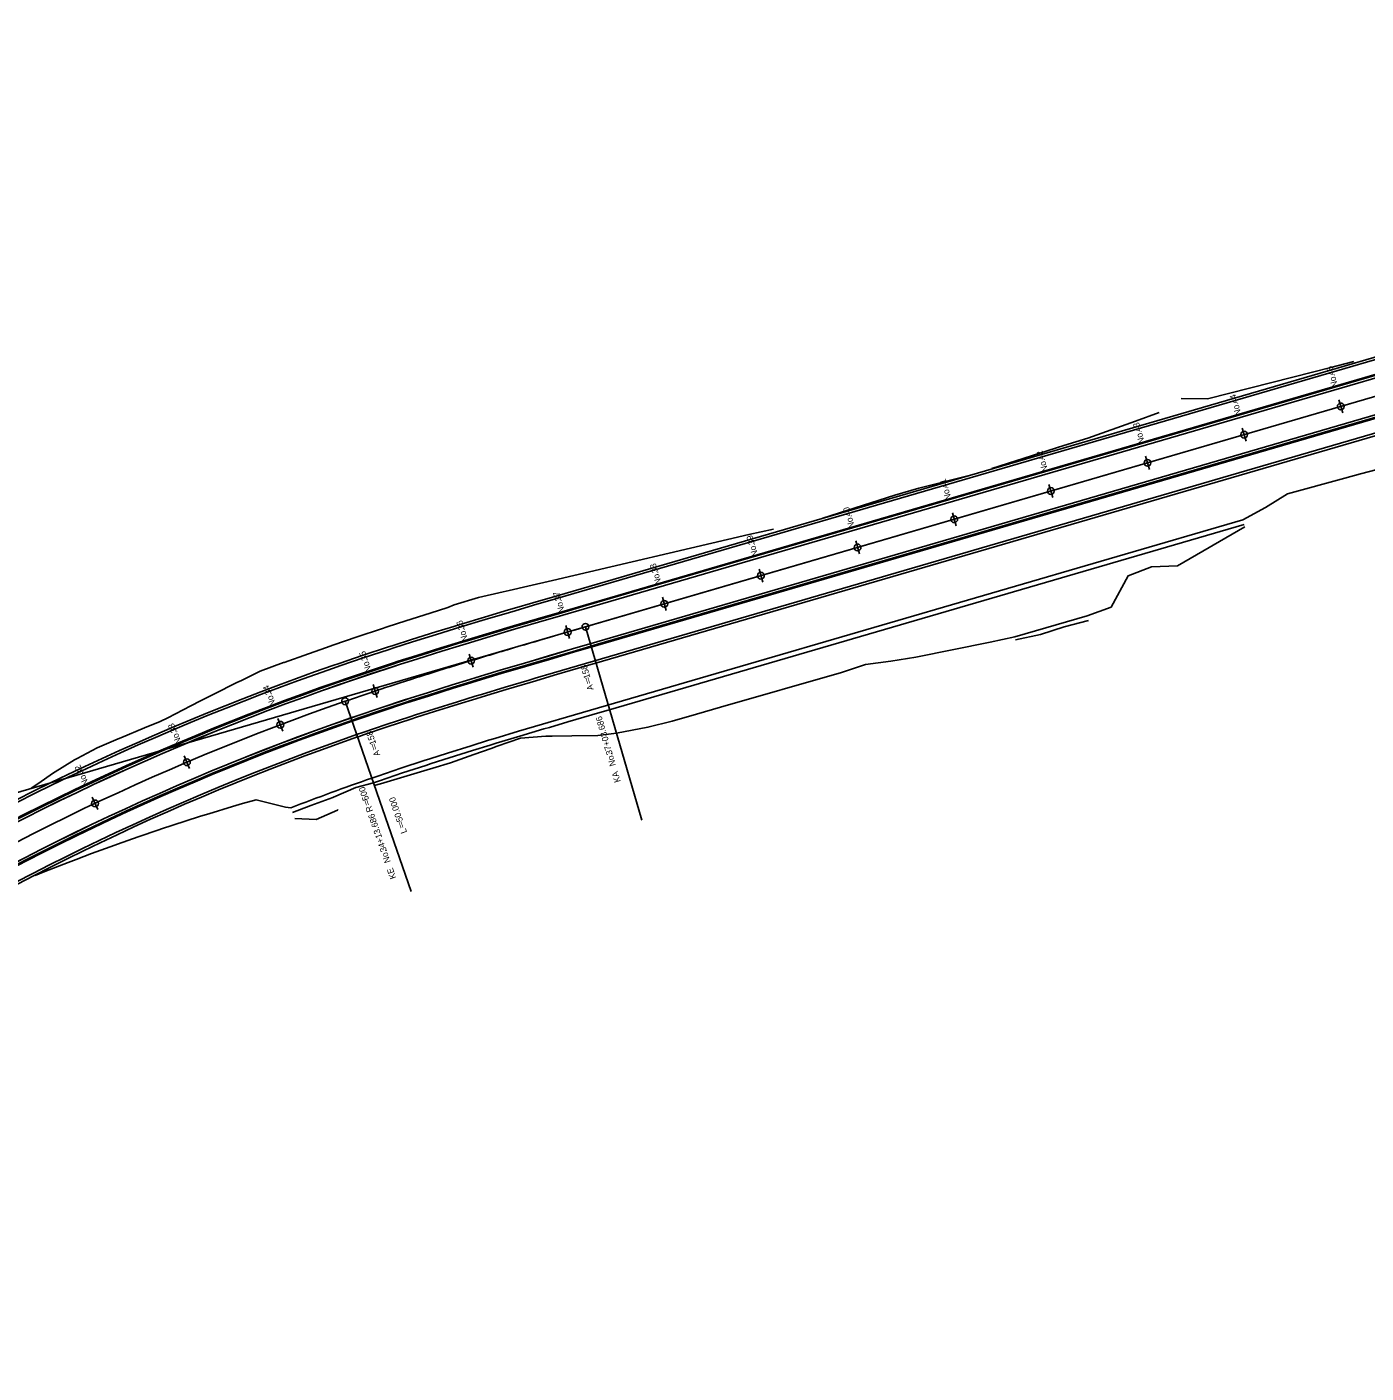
# Model space of a CAD drawing. Extents: x 46424 to 47578, y 10417 to 11548.
# Drawn here: x 46662.8 to 46928.8, y 10813.5 to 11080.9 of the extents above; entities that cross this region are included whole.
import ezdxf

# ---------------------------------------------------------------- set-up
doc = ezdxf.new("R2010")
doc.units = 0
for name, color, linetype in [('Default', 7, 'Continuous'), ('出典（地理院地図Vector）', 7, 'Continuous'), ('河川_人工水路(地下)（地理院地図Vector）', 7, 'Continuous'), ('現況_地形', 7, 'Continuous'), ('現況_地形_三角形', 7, 'Continuous'), ('現況_地形_三角形_頂点', 7, 'Continuous'), ('現況_地形_低い点', 7, 'Continuous'), ('現況_地形_単点標高', 7, 'Continuous'), ('現況_地形_等高線_マイナー', 7, 'Continuous'), ('等高線等深線_等高線_補助曲線通常部（地理院地図Vector）', 7, 'Continuous'), ('設計図面_測点 ラベル メジャー', 7, 'Continuous'), ('設計図面_測点 印 メジャー', 7, 'Continuous')]:
    doc.layers.add(name, color=color, linetype=linetype)

msp = doc.modelspace()

# ---------------------------------------------------------------- linework, layer by layer
at = {"layer": 'Default'}
for p, q in [((46606.99, 10913.06), (47182.22, 11080.85)), ((46773.73, 10961.69), (47084.04, 11052.21)), ((46923.79, 11005.47), (46923.79, 11005.47)), ((46904.59, 10999.87), (46904.59, 10999.87)), ((46885.39, 10994.27), (46885.39, 10994.27)), ((46866.19, 10988.67), (46866.19, 10988.67)), ((46846.99, 10983.06), (46846.99, 10983.06)), ((46827.79, 10977.46), (46827.79, 10977.46)), ((46808.59, 10971.86), (46808.59, 10971.86)), ((46789.39, 10966.26), (46789.39, 10966.26)), ((46770.19, 10960.66), (46770.19, 10960.66)), ((46773.73, 10961.69), (46773.73, 10961.69)), ((46773.73, 10961.69), (46784.93, 10923.29)), ((46751.02, 10954.98), (46751.02, 10954.98)), ((46725.98, 10946.9), (46725.98, 10946.9)), ((46725.98, 10946.9), (46739.09, 10909.1)), ((46725.98, 10946.9), (46739.09, 10909.1)), ((46731.96, 10948.93), (46731.96, 10948.93)), ((46713.11, 10942.24), (46713.11, 10942.24)), ((46694.55, 10934.8), (46694.55, 10934.8)), ((46676.3, 10926.62), (46676.3, 10926.62))]:
    msp.add_line(p, q, dxfattribs=at)
for centre in [(46923.79, 11005.47), (46904.59, 10999.87), (46885.39, 10994.27), (46866.19, 10988.67), (46846.99, 10983.06), (46827.79, 10977.46), (46808.59, 10971.86), (46789.39, 10966.26), (46770.19, 10960.66), (46773.73, 10961.69), (46751.02, 10954.98), (46731.96, 10948.93), (46725.98, 10946.9), (46713.11, 10942.24), (46694.55, 10934.8), (46676.3, 10926.62)]:
    msp.add_circle(centre, 0.675, dxfattribs=at)
msp.add_arc((46889.81, 10474.5), 500, 109.127, 136.5076, dxfattribs=at)
msp.add_arc((46889.81, 10474.5), 500, 109.127, 136.5076, dxfattribs=at)
msp.add_open_spline([(46725.98, 10946.9), (46727.95, 10947.58), (46731.89, 10948.92), (46739.81, 10951.51), (46749.76, 10954.62), (46759.74, 10957.6), (46767.73, 10959.94), (46771.73, 10961.11), (46773.73, 10961.69)], degree=3, dxfattribs=at)
msp.add_open_spline([(46725.98, 10946.9), (46727.95, 10947.58), (46731.89, 10948.92), (46739.81, 10951.51), (46749.76, 10954.62), (46759.74, 10957.6), (46767.73, 10959.94), (46771.73, 10961.11), (46773.73, 10961.69)], degree=3, dxfattribs=at)
at = {"layer": '出典（地理院地図Vector）'}
for points in [[(46723.52, 10953.98), (46724.78, 10954.42), (46729.58, 10956.04), (46734.39, 10957.63), (46735.53, 10957.99), (46739.2, 10959.17), (46744.02, 10960.67), (46747.57, 10961.77), (46748.84, 10962.15), (46753.66, 10963.6), (46758.47, 10965.04), (46759.61, 10965.37), (46763.28, 10966.45), (46768.09, 10967.86), (46772.89, 10969.26), (47081.94, 11059.41)], [(46728.44, 10939.81), (46729.66, 10940.23), (46734.33, 10941.81), (46739.02, 10943.36), (46740.14, 10943.72), (46743.73, 10944.87), (46748.46, 10946.35), (46751.95, 10947.42), (46753.2, 10947.8), (46757.96, 10949.23), (46762.73, 10950.65), (46763.86, 10950.99), (46767.51, 10952.06), (46772.3, 10953.46), (46777.09, 10954.86), (47086.14, 11045.01)]]:
    msp.add_lwpolyline(points, dxfattribs=at)
for radius in [507.5, 492.5]:
    msp.add_arc((46889.81, 10474.5), radius, 109.127, 136.5076, dxfattribs=at)
at = {"layer": '河川_人工水路(地下)（地理院地図Vector）'}
msp.add_line((46773.73, 10961.69), (47084.04, 11052.21), dxfattribs=at)
msp.add_arc((46889.81, 10474.5), 500, 109.127, 136.5076, dxfattribs=at)
msp.add_open_spline([(46725.98, 10946.9), (46727.95, 10947.58), (46731.89, 10948.92), (46739.81, 10951.51), (46749.76, 10954.62), (46759.74, 10957.6), (46767.73, 10959.94), (46771.73, 10961.11), (46773.73, 10961.69)], degree=3, dxfattribs=at)
at = {"layer": '現況_地形'}
for points in [[(46724.83, 10950.21), (46726.08, 10950.64), (46730.85, 10952.26), (46735.62, 10953.83), (46736.76, 10954.2), (46740.41, 10955.36), (46745.2, 10956.86), (46748.74, 10957.95), (46750, 10958.33), (46754.8, 10959.78), (46759.6, 10961.21), (46760.74, 10961.55), (46764.41, 10962.63), (46769.21, 10964.03), (46774.01, 10965.43), (47083.06, 11055.58)], [(46724.83, 10950.2), (46726.08, 10950.63), (46730.85, 10952.25), (46735.63, 10953.82), (46736.76, 10954.19), (46740.41, 10955.35), (46745.2, 10956.85), (46748.74, 10957.94), (46750, 10958.33), (46754.8, 10959.77), (46759.61, 10961.2), (46760.75, 10961.54), (46764.41, 10962.62), (46769.21, 10964.02), (46774.01, 10965.42), (47083.06, 11055.57)], [(46727.13, 10943.59), (46728.36, 10944.02), (46733.06, 10945.61), (46737.79, 10947.16), (46738.91, 10947.53), (46742.52, 10948.68), (46747.27, 10950.17), (46750.78, 10951.25), (46752.04, 10951.63), (46756.81, 10953.07), (46761.59, 10954.49), (46762.73, 10954.82), (46766.38, 10955.9), (46771.18, 10957.3), (46775.97, 10958.7), (47085.02, 11048.85)], [(46727.13, 10943.58), (46728.36, 10944.01), (46733.07, 10945.6), (46737.79, 10947.15), (46738.91, 10947.52), (46742.53, 10948.67), (46747.28, 10950.16), (46750.79, 10951.24), (46752.04, 10951.62), (46756.81, 10953.06), (46761.59, 10954.48), (46762.73, 10954.81), (46766.38, 10955.89), (46771.18, 10957.29), (46775.98, 10958.69), (47085.03, 11048.84)]]:
    msp.add_lwpolyline(points, dxfattribs=at)
for radius in [503.51, 503.5, 496.5, 496.49]:
    msp.add_arc((46889.81, 10474.5), radius, 109.127, 136.5076, dxfattribs=at)
at = {"layer": '現況_地形_三角形'}
msp.add_lwpolyline([(46854.47, 10993.15), (46864, 10996.17), (46868.77, 10997.68), (46873.54, 10999.2), (46882.98, 11002.55), (46887.68, 11004.29)], dxfattribs=at)
at = {"layer": '現況_地形_三角形_頂点'}
for points in [[(46892.07, 11007.08), (46897.3, 11007.01), (46918.45, 11012.36), (46921.55, 11013.14), (46926.4, 11014.39)], [(46731.27, 10931.64), (46732.47, 10932.05), (46737.07, 10933.61), (46741.69, 10935.13), (46742.79, 10935.49), (46746.34, 10936.62), (46751.02, 10938.08), (46754.48, 10939.15), (46755.72, 10939.53), (46760.44, 10940.95), (46765.18, 10942.36), (46766.31, 10942.69), (46769.94, 10943.76), (46774.72, 10945.16), (46779.52, 10946.56), (46904.32, 10982.96), (46908.81, 10985.42), (46913.22, 10988.14), (46924.6, 10991.25), (46927.69, 10992.09), (46932.55, 10993.31)], [(46820.88, 10983.3), (46835.18, 10987.84), (46839.99, 10989.24), (46849.68, 10991.71)], [(46715.55, 10924.81), (46719.17, 10926.19), (46723.55, 10927.82), (46723.7, 10927.88), (46728.14, 10929.8), (46731.6, 10930.69), (46732.8, 10931.11), (46737.38, 10932.66), (46742, 10934.18), (46743.1, 10934.54), (46746.64, 10935.67), (46751.31, 10937.13), (46754.77, 10938.19), (46756.01, 10938.57), (46760.72, 10939.99), (46765.46, 10941.4), (46766.59, 10941.73), (46770.22, 10942.8), (46775, 10944.2), (46779.8, 10945.6), (46904.6, 10982)], [(46663.64, 10929.62), (46665.11, 10930.64), (46667.88, 10932.53), (46672.22, 10935.25), (46672.74, 10935.55), (46676.73, 10937.65), (46680.89, 10939.43), (46681.42, 10939.65), (46686.12, 10941.61), (46689.22, 10942.88), (46690.79, 10943.64), (46695.34, 10946), (46697.28, 10946.99), (46699.9, 10948.32), (46704.49, 10950.61), (46705.4, 10951.05), (46709.1, 10952.87), (46713.73, 10954.58), (46713.89, 10954.64), (46718.71, 10956.36), (46722.27, 10957.6), (46723.54, 10958.04), (46728.37, 10959.68), (46733.2, 10961.29), (46734.35, 10961.66), (46738.04, 10962.86), (46742.86, 10964.41), (46746.42, 10965.53), (46747.65, 10966.08), (46752.48, 10967.53), (46757.4, 10968.67), (46758.56, 10968.93), (46762.31, 10969.79), (46767.2, 10970.9), (46806.21, 10980.05), (46811.11, 10981.09)], [(46731.77, 10930.2), (46732.99, 10930.54), (46737.63, 10931.93), (46742.28, 10933.32), (46743.38, 10933.65), (46746.95, 10934.71), (46751.56, 10936.33), (46754.97, 10937.54), (46756.19, 10937.97), (46760.84, 10939.61), (46765.89, 10939.95), (46767.11, 10939.97), (46771.04, 10940.03), (46776.2, 10940.1), (46779.89, 10940.59), (46786.13, 10941.74), (46790.98, 10942.96), (46795.79, 10944.35), (46800.59, 10945.74), (46824.62, 10952.64), (46829.37, 10954.21), (46834.38, 10954.88), (46839.35, 10955.7), (46854.12, 10958.65), (46859.02, 10959.7), (46873.42, 10963.9), (46878.14, 10965.58), (46881.52, 10971.83), (46886.2, 10973.64), (46891.35, 10973.83), (46904.73, 10981.55)], [(46859.18, 10959.14), (46864.1, 10960.14), (46868.85, 10961.71), (46873.7, 10962.94)], [(46664.42, 10912.32), (46666.36, 10913.09), (46670.96, 10914.89), (46672.56, 10915.5), (46675.58, 10916.64), (46680.21, 10918.33), (46680.76, 10918.52), (46684.86, 10919.97), (46689, 10921.38), (46689.52, 10921.55), (46694.2, 10923.08), (46697.28, 10924.06), (46698.89, 10924.56), (46703.59, 10925.98), (46705.6, 10926.57), (46708.3, 10927.35), (46714.11, 10925.88), (46715.19, 10925.74)], [(46716.01, 10923.62), (46720.22, 10923.43), (46724.49, 10925.26), (46724.61, 10925.4)]]:
    msp.add_lwpolyline(points, dxfattribs=at)
msp.add_arc((46889.81, 10474.5), 483.85, 109.127, 111.1552, dxfattribs=at)
at = {"layer": '現況_地形_低い点'}
for points in [[(46724.67, 10950.68), (46725.92, 10951.11), (46730.69, 10952.72), (46735.47, 10954.3), (46736.61, 10954.66), (46740.26, 10955.83), (46745.06, 10957.33), (46748.59, 10958.42), (46749.86, 10958.8), (46754.66, 10960.25), (46759.46, 10961.68), (46760.6, 10962.02), (46764.27, 10963.1), (46769.07, 10964.5), (46773.87, 10965.9), (47082.92, 11056.05)], [(46727.29, 10943.12), (46728.52, 10943.54), (46733.22, 10945.13), (46737.94, 10946.69), (46739.06, 10947.05), (46742.67, 10948.2), (46747.42, 10949.69), (46750.93, 10950.77), (46752.18, 10951.15), (46756.95, 10952.59), (46761.73, 10954.01), (46762.87, 10954.34), (46766.52, 10955.42), (46771.32, 10956.82), (46776.11, 10958.22), (47085.16, 11048.37)]]:
    msp.add_lwpolyline(points, dxfattribs=at)
for radius in [504, 496]:
    msp.add_arc((46889.81, 10474.5), radius, 109.127, 136.5076, dxfattribs=at)
at = {"layer": '現況_地形_単点標高'}
for points in [[(46723.69, 10953.51), (46724.94, 10953.94), (46729.74, 10955.57), (46734.55, 10957.15), (46735.69, 10957.52), (46739.36, 10958.69), (46744.17, 10960.2), (46747.72, 10961.29), (46748.98, 10961.67), (46753.8, 10963.13), (46758.61, 10964.56), (46759.76, 10964.9), (46763.43, 10965.97), (46768.23, 10967.38), (46773.03, 10968.78), (47082.08, 11058.93)], [(46724.6, 10950.86), (46725.85, 10951.3), (46730.63, 10952.91), (46735.41, 10954.49), (46736.55, 10954.85), (46740.2, 10956.02), (46745, 10957.52), (46748.54, 10958.61), (46749.8, 10958.99), (46754.6, 10960.44), (46759.41, 10961.87), (46760.55, 10962.21), (46764.21, 10963.29), (46769.02, 10964.69), (46773.82, 10966.09), (47082.87, 11056.25)], [(46727.36, 10942.93), (46728.59, 10943.35), (46733.29, 10944.94), (46738, 10946.5), (46739.12, 10946.86), (46742.74, 10948.01), (46747.48, 10949.5), (46750.99, 10950.58), (46752.24, 10950.96), (46757.01, 10952.4), (46761.79, 10953.82), (46762.93, 10954.15), (46766.58, 10955.23), (46771.37, 10956.63), (46776.17, 10958.03), (47085.22, 11048.18)], [(46728.27, 10940.28), (46729.5, 10940.71), (46734.17, 10942.29), (46738.87, 10943.83), (46739.98, 10944.19), (46743.58, 10945.34), (46748.31, 10946.82), (46751.81, 10947.9), (46753.06, 10948.28), (46757.81, 10949.71), (46762.58, 10951.13), (46763.72, 10951.47), (46767.37, 10952.54), (46772.16, 10953.94), (46776.95, 10955.34), (47086, 11045.49)]]:
    msp.add_lwpolyline(points, dxfattribs=at)
for radius in [507, 504.2, 495.8, 493]:
    msp.add_arc((46889.81, 10474.5), radius, 109.127, 136.5076, dxfattribs=at)
at = {"layer": '現況_地形_等高線_マイナー'}
for points in [[(46724.66, 10950.69), (46725.91, 10951.13), (46730.68, 10952.74), (46735.47, 10954.32), (46736.6, 10954.68), (46740.25, 10955.85), (46745.05, 10957.35), (46748.59, 10958.44), (46749.85, 10958.82), (46754.65, 10960.27), (46759.46, 10961.7), (46760.6, 10962.04), (46764.26, 10963.12), (46769.07, 10964.52), (46773.87, 10965.92), (47082.92, 11056.07)], [(46727.3, 10943.1), (46728.53, 10943.52), (46733.23, 10945.12), (46737.95, 10946.67), (46739.07, 10947.03), (46742.68, 10948.18), (46747.43, 10949.67), (46750.94, 10950.75), (46752.19, 10951.13), (46756.96, 10952.57), (46761.74, 10953.99), (46762.87, 10954.33), (46766.53, 10955.4), (46771.32, 10956.8), (46776.12, 10958.2), (47085.17, 11048.35)]]:
    msp.add_lwpolyline(points, dxfattribs=at)
for radius in [504.02, 495.98]:
    msp.add_arc((46889.81, 10474.5), radius, 109.127, 136.5076, dxfattribs=at)
at = {"layer": '等高線等深線_等高線_補助曲線通常部（地理院地図Vector）'}
msp.add_line((46773.73, 10961.69), (47084.04, 11052.21), dxfattribs=at)
msp.add_arc((46889.81, 10474.5), 500, 109.127, 136.5076, dxfattribs=at)
msp.add_open_spline([(46725.98, 10946.9), (46727.95, 10947.58), (46731.89, 10948.92), (46739.81, 10951.51), (46749.76, 10954.62), (46759.74, 10957.6), (46767.73, 10959.94), (46771.73, 10961.11), (46773.73, 10961.69)], degree=3, dxfattribs=at)
at = {"layer": '設計図面_測点 印 メジャー'}
for p, q in [((46923.41, 11006.76), (46924.17, 11004.17)), ((46904.21, 11001.16), (46904.97, 10998.57)), ((46885.02, 10995.56), (46885.77, 10992.97)), ((46865.82, 10989.96), (46866.57, 10987.37)), ((46846.62, 10984.36), (46847.37, 10981.77)), ((46827.42, 10978.76), (46828.17, 10976.17)), ((46808.22, 10973.16), (46808.97, 10970.57)), ((46789.02, 10967.56), (46789.77, 10964.97)), ((46769.82, 10961.96), (46770.57, 10959.37)), ((46750.63, 10956.27), (46751.41, 10953.68)), ((46731.53, 10950.21), (46732.38, 10947.65)), ((46712.63, 10943.5), (46713.59, 10940.97)), ((46694.02, 10936.04), (46695.08, 10933.55)), ((46675.72, 10927.84), (46676.87, 10925.4))]:
    msp.add_line(p, q, dxfattribs=at)

# ---------------------------------------------------------------- texts
at = {"layer": 'Default'}
for s, rotation, p in [('158', 106.2622, (46774.72, 10951.61)), ('A＝', 106.2622, (46775.4, 10949.27)), ('37+03.686', 106.2622, (46779.15, 10936.43)), ('158', 109.127, (46732.19, 10938.51)), ('A＝', 109.127, (46732.99, 10936.21)), ('\u3000No.', 106.2622, (46780.29, 10932.53)), ('KA', 106.2622, (46780.74, 10930.97)), ('500', 109.127, (46730.75, 10927.42)), ('R＝', 109.127, (46731.55, 10925.11)), ('50.000', 109.127, (46737.51, 10923.18)), ('34+13.686', 109.127, (46734.29, 10917.21)), ('L＝', 109.127, (46738.31, 10920.88)), ('\u3000No.', 109.127, (46735.62, 10913.38)), ('KE', 109.127, (46736.15, 10911.84))]:
    msp.add_text(s, height=1.25, rotation=rotation, dxfattribs=at).set_placement(p)
at = {"layer": '設計図面_測点 ラベル メジャー'}
for s, rotation, p in [('45', 106.2622, (46922.59, 11011.82)), ('No.', 106.2622, (46923.27, 11009.48)), ('44', 106.2622, (46903.39, 11006.22)), ('No.', 106.2622, (46904.07, 11003.88)), ('43', 106.2622, (46884.19, 11000.62)), ('No.', 106.2622, (46884.87, 10998.28)), ('42', 106.2622, (46864.99, 10995.02)), ('No.', 106.2622, (46865.67, 10992.68)), ('41', 106.2622, (46845.79, 10989.42)), ('No.', 106.2622, (46846.47, 10987.08)), ('40', 106.2622, (46826.59, 10983.82)), ('No.', 106.2622, (46827.27, 10981.48)), ('39', 106.2622, (46807.39, 10978.22)), ('No.', 106.2622, (46808.07, 10975.88)), ('38', 106.2622, (46788.19, 10972.62)), ('No.', 106.2622, (46788.87, 10970.28)), ('37', 106.2778, (46768.99, 10967.02)), ('No.', 106.2778, (46769.67, 10964.68)), ('36', 106.9051, (46749.75, 10961.32)), ('No.', 106.9051, (46750.45, 10958.99)), ('35', 108.4492, (46730.51, 10955.23)), ('No.', 108.4492, (46731.28, 10952.92)), ('34', 110.6953, (46711.42, 10948.48)), ('No.', 110.6953, (46712.28, 10946.2)), ('33', 112.9872, (46692.61, 10940.96)), ('No.', 112.9872, (46693.56, 10938.72)), ('32', 115.279, (46674.11, 10932.71)), ('No.', 115.279, (46675.15, 10930.5))]:
    msp.add_text(s, height=1.25, rotation=rotation, dxfattribs=at).set_placement(p)

doc.saveas('drawing.dxf')
